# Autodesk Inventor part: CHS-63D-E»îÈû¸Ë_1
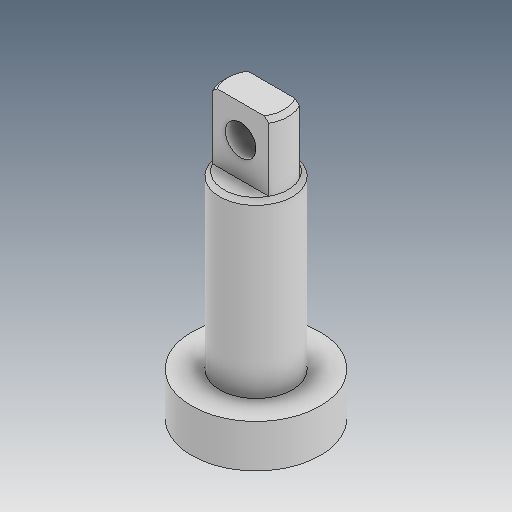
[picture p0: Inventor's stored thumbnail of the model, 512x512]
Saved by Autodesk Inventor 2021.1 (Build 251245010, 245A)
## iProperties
Created: 2019-05
Part Number: CHS-63D-E»îÈû¸Ë_1
Material: Ogólny
Document SubType Name: Modeling
Designer: user
Density: 1 g/cm^3
Appearance: Domyślna
Author: user
Revision Number: ÈÎºÎ
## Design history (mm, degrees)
feature "ÊäÈë1"
feature "ÊäÈë2"
node "Bryła1"
node "Bryła2"
